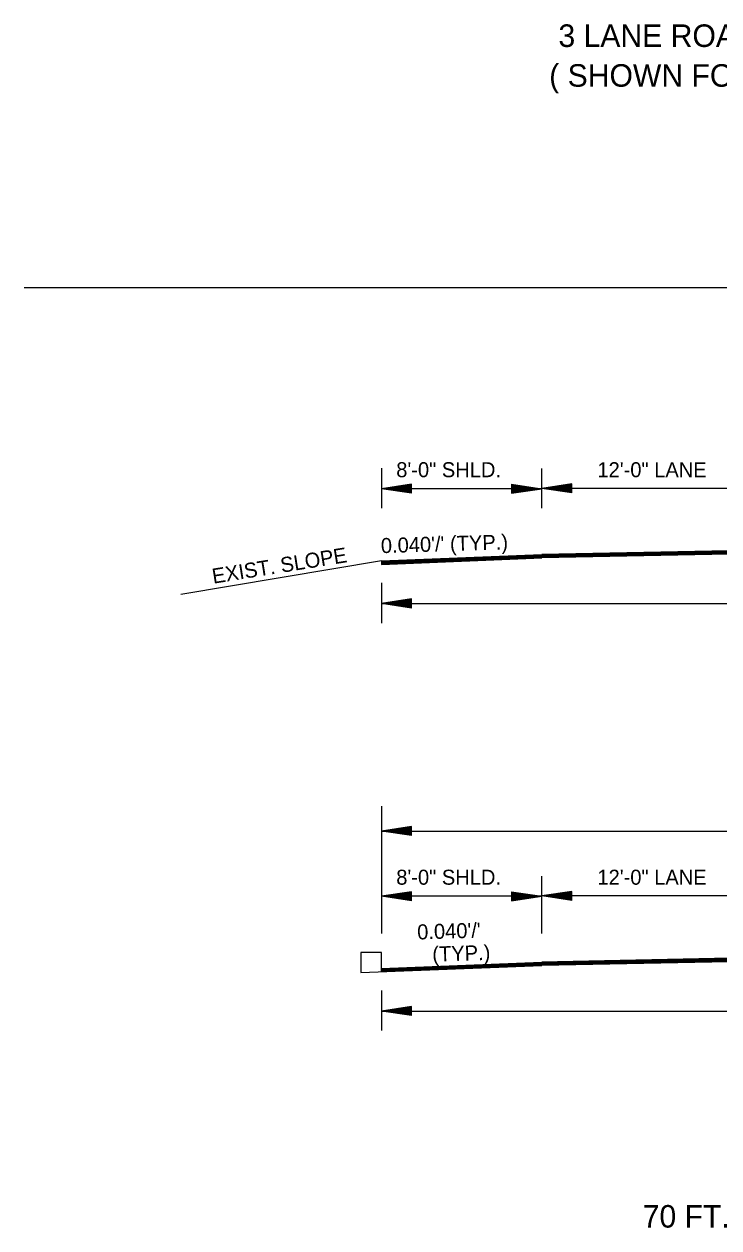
# Model space of a CAD drawing. Extents: x 550980 to 1930787, y -1972975 to 596640.
# Drawn here: x 551026 to 551373, y -1956536 to -1955935 of the extents above; entities that cross this region are included whole.
import ezdxf

# ---------------------------------------------------------------- set-up
doc = ezdxf.new("R2010")
doc.units = 0
doc.layers.add('R_Border', color=7, linetype='Continuous')
doc.layers.add('R_Draft', color=7, linetype='Continuous')

msp = doc.modelspace()

# ---------------------------------------------------------------- linework, layer by layer
at = {"layer": 'R_Border'}
for p, q in [((551025.9, -1956066.24), (552087.17, -1956066.24)), ((551204.25, -1956398.42), (551194.08, -1956398.42)), ((551194.08, -1956398.42), (551194.08, -1956408.43)), ((551204.25, -1956407.83), (551204.25, -1956398.42))]:
    msp.add_line(p, q, dxfattribs=at)
at = {"layer": 'R_Draft'}
for p, q in [((551204.25, -1956156.45), (551204.25, -1956176.45)), ((551284.29, -1956176.45), (551284.29, -1956156.73)), ((551219.29, -1956164.54), (551204.29, -1956166.79)), ((551219.29, -1956164.92), (551206.79, -1956166.79)), ((551219.29, -1956169.04), (551219.29, -1956164.54)), ((551269.29, -1956164.54), (551284.29, -1956166.79)), ((551269.29, -1956164.54), (551269.29, -1956169.04)), ((551269.29, -1956164.92), (551281.78, -1956166.79)), ((551299.29, -1956164.37), (551284.29, -1956166.62)), ((551299.29, -1956164.75), (551286.79, -1956166.62)), ((551299.29, -1956165.13), (551289.37, -1956166.62)), ((551299.29, -1956168.87), (551299.29, -1956164.37)), ((551284.29, -1956166.79), (551204.29, -1956166.79)), ((551219.29, -1956169.04), (551204.29, -1956166.79)), ((551219.29, -1956168.67), (551206.79, -1956166.79)), ((551219.29, -1956165.3), (551209.37, -1956166.79)), ((551219.29, -1956168.29), (551209.37, -1956166.79)), ((551219.29, -1956165.68), (551211.87, -1956166.79)), ((551219.29, -1956167.91), (551211.87, -1956166.79)), ((551219.29, -1956166.06), (551214.41, -1956166.79)), ((551219.29, -1956167.52), (551214.41, -1956166.79)), ((551219.29, -1956166.44), (551216.92, -1956166.79)), ((551219.29, -1956167.15), (551216.92, -1956166.79)), ((551269.29, -1956165.3), (551279.2, -1956166.79)), ((551269.29, -1956165.68), (551276.7, -1956166.79)), ((551269.29, -1956166.07), (551274.16, -1956166.79)), ((551269.29, -1956166.44), (551271.66, -1956166.79)), ((551269.29, -1956169.04), (551284.29, -1956166.79)), ((551269.29, -1956167.53), (551274.16, -1956166.79)), ((551269.29, -1956168.29), (551279.2, -1956166.79)), ((551269.29, -1956168.67), (551281.78, -1956166.79)), ((551269.29, -1956167.91), (551276.7, -1956166.79)), ((551269.29, -1956167.15), (551271.66, -1956166.79)), ((551404.29, -1956166.62), (551284.29, -1956166.62)), ((551299.29, -1956168.87), (551284.29, -1956166.62)), ((551299.29, -1956168.5), (551286.79, -1956166.62)), ((551299.29, -1956168.12), (551289.37, -1956166.62)), ((551299.29, -1956165.51), (551291.87, -1956166.62)), ((551299.29, -1956167.74), (551291.87, -1956166.62)), ((551299.29, -1956165.89), (551294.41, -1956166.62)), ((551299.29, -1956167.35), (551294.41, -1956166.62)), ((551299.29, -1956166.27), (551296.92, -1956166.62)), ((551299.29, -1956166.98), (551296.92, -1956166.62)), ((551554.29, -1956194.23), (551284.29, -1956199.63)), ((551554.29, -1956194.53), (551284.29, -1956199.93)), ((551554.3, -1956194.83), (551284.29, -1956200.23)), ((551554.3, -1956195.13), (551284.29, -1956200.53)), ((551204.25, -1956202.83), (551284.29, -1956199.63)), ((551204.25, -1956203.13), (551284.29, -1956199.93)), ((551204.25, -1956203.43), (551284.29, -1956200.23)), ((551204.25, -1956203.73), (551284.29, -1956200.53)), ((551204.25, -1956204.03), (551284.29, -1956200.83)), ((551204.25, -1956204.33), (551284.29, -1956201.13)), ((551554.31, -1956195.43), (551284.29, -1956200.83)), ((551554.32, -1956195.73), (551284.29, -1956201.13)), ((551554.32, -1956195.93), (551284.29, -1956201.33)), ((551204.25, -1956202.83), (551104.18, -1956219.51)), ((551204.25, -1956204.53), (551284.29, -1956201.33)), ((551204.25, -1956202.83), (551204.25, -1956204.53)), ((551204.29, -1956213.84), (551204.29, -1956233.84)), ((551204.25, -1956224.09), (551904.29, -1956224.09)), ((551219.29, -1956221.84), (551204.29, -1956224.09)), ((551219.29, -1956226.34), (551204.29, -1956224.09)), ((551219.29, -1956222.21), (551206.79, -1956224.09)), ((551219.29, -1956225.96), (551206.79, -1956224.09)), ((551219.29, -1956222.6), (551209.37, -1956224.09)), ((551219.29, -1956225.58), (551209.37, -1956224.09)), ((551219.29, -1956222.97), (551211.87, -1956224.09)), ((551219.29, -1956225.21), (551211.87, -1956224.09)), ((551219.29, -1956223.35), (551214.41, -1956224.09)), ((551219.29, -1956224.82), (551214.41, -1956224.09)), ((551219.29, -1956223.74), (551216.92, -1956224.09)), ((551219.29, -1956224.44), (551216.92, -1956224.09)), ((551219.29, -1956226.34), (551219.29, -1956221.84)), ((551204.25, -1956325.23), (551204.25, -1956388.95)), ((551204.25, -1956337.76), (551904.29, -1956337.76)), ((551219.29, -1956335.51), (551204.29, -1956337.76)), ((551219.29, -1956340.01), (551204.29, -1956337.76)), ((551219.29, -1956335.88), (551206.79, -1956337.76)), ((551219.29, -1956339.63), (551206.79, -1956337.76)), ((551219.29, -1956336.26), (551209.37, -1956337.76)), ((551219.29, -1956339.25), (551209.37, -1956337.76)), ((551219.29, -1956336.64), (551211.87, -1956337.76)), ((551219.29, -1956338.87), (551211.87, -1956337.76)), ((551219.29, -1956337.02), (551214.41, -1956337.76)), ((551219.29, -1956338.48), (551214.41, -1956337.76)), ((551219.29, -1956337.4), (551216.92, -1956337.76)), ((551219.29, -1956338.11), (551216.92, -1956337.76)), ((551219.29, -1956340.01), (551219.29, -1956335.51)), ((551284.29, -1956388.95), (551284.29, -1956360.23)), ((551219.29, -1956368.04), (551204.29, -1956370.29)), ((551219.29, -1956368.41), (551206.79, -1956370.29)), ((551219.29, -1956368.8), (551209.37, -1956370.29)), ((551219.29, -1956369.17), (551211.87, -1956370.29)), ((551219.29, -1956369.55), (551214.41, -1956370.29)), ((551219.29, -1956372.54), (551219.29, -1956368.04)), ((551269.29, -1956368.04), (551284.29, -1956370.29)), ((551269.29, -1956368.04), (551269.29, -1956372.54)), ((551269.29, -1956368.41), (551281.78, -1956370.29)), ((551269.29, -1956368.8), (551279.2, -1956370.29)), ((551269.29, -1956369.17), (551276.7, -1956370.29)), ((551269.29, -1956369.56), (551274.16, -1956370.29)), ((551299.29, -1956367.87), (551284.29, -1956370.12)), ((551299.29, -1956368.24), (551286.79, -1956370.12)), ((551299.29, -1956368.63), (551289.37, -1956370.12)), ((551299.29, -1956369), (551291.87, -1956370.12)), ((551299.29, -1956369.38), (551294.41, -1956370.12)), ((551299.29, -1956372.37), (551299.29, -1956367.87)), ((551284.29, -1956370.29), (551204.29, -1956370.29)), ((551219.29, -1956372.54), (551204.29, -1956370.29)), ((551219.29, -1956372.16), (551206.79, -1956370.29)), ((551219.29, -1956371.78), (551209.37, -1956370.29)), ((551219.29, -1956371.41), (551211.87, -1956370.29)), ((551219.29, -1956371.02), (551214.41, -1956370.29)), ((551219.29, -1956369.94), (551216.92, -1956370.29)), ((551219.29, -1956370.64), (551216.92, -1956370.29)), ((551269.29, -1956369.94), (551271.66, -1956370.29)), ((551269.29, -1956372.54), (551284.29, -1956370.29)), ((551269.29, -1956371.02), (551274.16, -1956370.29)), ((551269.29, -1956371.78), (551279.2, -1956370.29)), ((551269.29, -1956372.16), (551281.78, -1956370.29)), ((551269.29, -1956371.41), (551276.7, -1956370.29)), ((551269.29, -1956370.64), (551271.66, -1956370.29)), ((551404.29, -1956370.12), (551284.29, -1956370.12)), ((551299.29, -1956372.37), (551284.29, -1956370.12)), ((551299.29, -1956371.99), (551286.79, -1956370.12)), ((551299.29, -1956371.61), (551289.37, -1956370.12)), ((551299.29, -1956371.24), (551291.87, -1956370.12)), ((551299.29, -1956370.85), (551294.41, -1956370.12)), ((551299.29, -1956369.77), (551296.92, -1956370.12)), ((551299.29, -1956370.47), (551296.92, -1956370.12)), ((551554.29, -1956397.72), (551284.29, -1956403.12)), ((551554.29, -1956398.02), (551284.29, -1956403.42)), ((551554.3, -1956398.32), (551284.29, -1956403.72)), ((551554.3, -1956398.62), (551284.29, -1956404.02)), ((551554.31, -1956398.92), (551284.29, -1956404.32)), ((551554.32, -1956399.22), (551284.29, -1956404.62)), ((551554.32, -1956399.42), (551284.29, -1956404.82)), ((551194.08, -1956408.43), (551284.29, -1956404.82)), ((551204.25, -1956406.33), (551284.29, -1956403.12)), ((551204.25, -1956406.63), (551284.29, -1956403.42)), ((551204.25, -1956406.93), (551284.29, -1956403.72)), ((551204.25, -1956407.23), (551284.29, -1956404.02)), ((551204.25, -1956407.53), (551284.29, -1956404.32)), ((551204.25, -1956407.83), (551284.29, -1956404.62)), ((551204.29, -1956417.33), (551204.29, -1956437.33)), ((551204.25, -1956427.58), (551904.29, -1956427.58)), ((551219.29, -1956425.33), (551204.29, -1956427.58)), ((551219.29, -1956429.83), (551204.29, -1956427.58)), ((551219.29, -1956425.71), (551206.79, -1956427.58)), ((551219.29, -1956429.46), (551206.79, -1956427.58)), ((551219.29, -1956426.09), (551209.37, -1956427.58)), ((551219.29, -1956429.07), (551209.37, -1956427.58)), ((551219.29, -1956426.46), (551211.87, -1956427.58)), ((551219.29, -1956428.7), (551211.87, -1956427.58)), ((551219.29, -1956426.85), (551214.41, -1956427.58)), ((551219.29, -1956428.31), (551214.41, -1956427.58)), ((551219.29, -1956427.23), (551216.92, -1956427.58)), ((551219.29, -1956427.93), (551216.92, -1956427.58)), ((551219.29, -1956429.83), (551219.29, -1956425.33))]:
    msp.add_line(p, q, dxfattribs=at)

# ---------------------------------------------------------------- texts
at = {"layer": 'R_Border'}
msp.add_text('( SHOWN FOR MOT)', height=11.25, dxfattribs=at).set_placement((551288.03, -1955966.03))
at = {"layer": 'R_Draft'}
for s, height, p in [('3 LANE ROADWAY', 11.25, (551292.64, -1955946.17)), ('8\'-0" SHLD.', 7.5, (551211.68, -1956161.02)), ('12\'-0" LANE', 7.5, (551312.1, -1956161.02)), ('8\'-0" SHLD.', 7.5, (551211.68, -1956364.52)), ('12\'-0" LANE', 7.5, (551312.1, -1956364.52)), ('70 FT. CLEAR ROADWAY BRIDGE - POLYMER OVERLAY', 11.25, (551334.7, -1956535.73))]:
    msp.add_text(s, height=height, dxfattribs=at).set_placement(p)
for s, rotation, p in [("0.040'/' (TYP.)", 1.70227, (551204.11, -1956198.96)), ('EXIST. SLOPE', 9.15344, (551120.37, -1956214.23)), ("0.040'/' ", 1.70227, (551222.24, -1956391.88)), ('(TYP.)', 1.70227, (551229.77, -1956402.91))]:
    msp.add_text(s, height=7.5, rotation=rotation, dxfattribs=at).set_placement(p)

doc.saveas('drawing.dxf')
